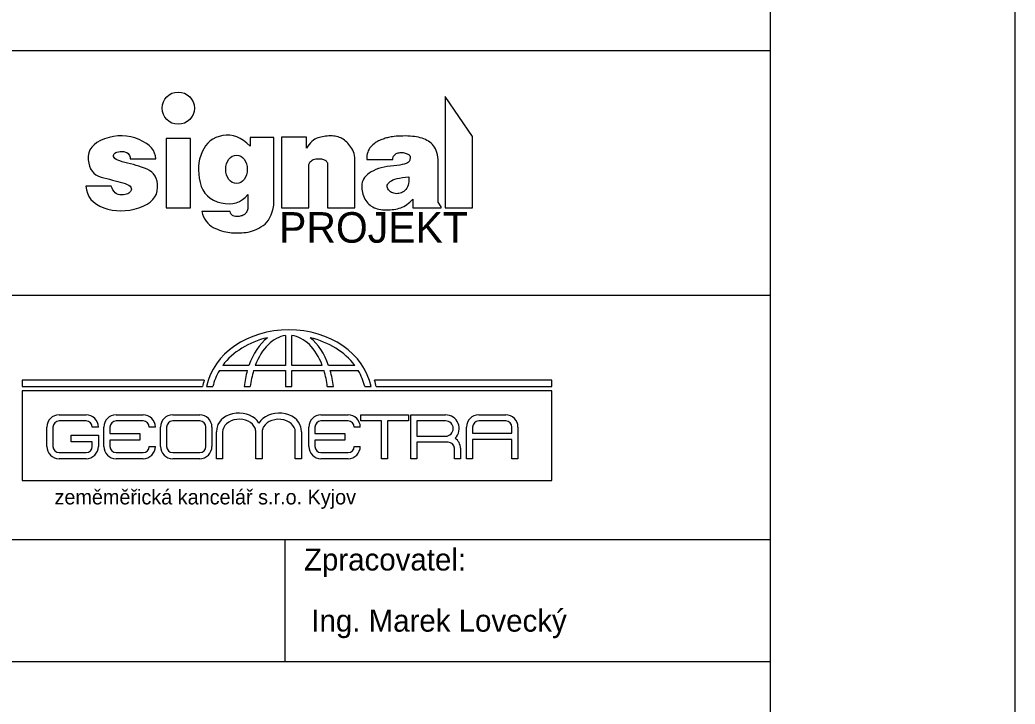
# Model space of a CAD drawing. Extents: x 2583 to 4283, y -3799 to -3355.
# Drawn here: x 3456.4 to 3537.7, y -3700 to -3644 of the extents above; entities that cross this region are included whole.
import ezdxf

# ---------------------------------------------------------------- set-up
doc = ezdxf.new("R2010")
doc.units = 0
for name, color, linetype in [('Default', 7, 'Continuous'), ('Vrstva 1', 7, 'Continuous'), ('Vrstva 11', 7, 'Continuous'), ('Vrstva 17', 7, 'Continuous'), ('Vrstva 6', 7, 'Continuous')]:
    doc.layers.add(name, color=color, linetype=linetype)

msp = doc.modelspace()

# ---------------------------------------------------------------- linework, layer by layer
at = {"layer": 'Default'}
msp.add_lwpolyline([(3327.684, -3798.543), (3537.684, -3798.543), (3537.684, -3501.543), (3327.684, -3501.543)], close=True, dxfattribs=at)
at = {"layer": 'Vrstva 1'}
msp.add_lwpolyline([(3347.684, -3521.543), (3517.684, -3521.543), (3517.684, -3781.543), (3347.684, -3781.543)], close=True, dxfattribs=at)
at = {"layer": 'Vrstva 11'}
for points in [[(3493.348, -3659.422), (3493.348, -3653.582), (3491.108, -3650.302), (3491.108, -3659.422), (3493.348, -3659.422)], [(3464.62, -3659.657), (3464.982, -3659.641), (3465.348, -3659.593), (3465.719, -3659.514), (3466.095, -3659.403), (3466.45, -3659.267), (3466.758, -3659.111), (3467.019, -3658.935), (3467.233, -3658.739), (3467.4, -3658.523), (3467.521, -3658.287), (3467.594, -3658.031), (3467.621, -3657.755), (3467.61, -3657.482), (3467.572, -3657.233), (3467.506, -3657.009), (3467.412, -3656.809), (3467.291, -3656.635), (3467.141, -3656.485), (3466.964, -3656.359), (3466.76, -3656.259), (3466.54, -3656.172), (3466.318, -3656.091), (3466.094, -3656.013), (3465.868, -3655.94), (3465.639, -3655.872), (3465.408, -3655.808), (3465.174, -3655.748), (3464.939, -3655.693), (3464.717, -3655.638), (3464.526, -3655.579), (3464.365, -3655.515), (3464.235, -3655.448), (3464.135, -3655.377), (3464.065, -3655.302), (3464.026, -3655.223), (3464.018, -3655.14), (3464.034, -3655.06), (3464.071, -3654.991), (3464.127, -3654.933), (3464.203, -3654.886), (3464.299, -3654.85), (3464.414, -3654.825), (3464.55, -3654.81), (3464.705, -3654.806), (3464.86, -3654.817), (3464.996, -3654.846), (3465.111, -3654.893), (3465.205, -3654.959), (3465.28, -3655.043), (3465.335, -3655.145), (3465.369, -3655.266), (3465.384, -3655.404), (3467.463, -3655.404), (3467.444, -3655.163), (3467.381, -3654.933), (3467.276, -3654.716), (3467.128, -3654.512), (3466.938, -3654.32), (3466.704, -3654.141), (3466.427, -3653.975), (3466.108, -3653.822), (3465.766, -3653.692), (3465.421, -3653.598), (3465.073, -3653.538), (3464.723, -3653.513), (3464.37, -3653.523), (3464.014, -3653.568), (3463.656, -3653.648), (3463.295, -3653.762), (3462.957, -3653.904), (3462.668, -3654.067), (3462.427, -3654.251), (3462.235, -3654.454), (3462.091, -3654.679), (3461.997, -3654.924), (3461.95, -3655.189), (3461.953, -3655.475), (3461.992, -3655.757), (3462.058, -3656.008), (3462.151, -3656.231), (3462.269, -3656.424), (3462.414, -3656.587), (3462.585, -3656.721), (3462.782, -3656.825), (3463.005, -3656.9), (3463.24, -3656.96), (3463.471, -3657.019), (3463.699, -3657.079), (3463.923, -3657.138), (3464.143, -3657.196), (3464.36, -3657.255), (3464.573, -3657.313), (3464.783, -3657.371), (3464.975, -3657.43), (3465.136, -3657.495), (3465.267, -3657.564), (3465.366, -3657.637), (3465.435, -3657.715), (3465.473, -3657.797), (3465.48, -3657.884), (3465.456, -3657.976), (3465.409, -3658.064), (3465.348, -3658.14), (3465.273, -3658.205), (3465.183, -3658.258), (3465.079, -3658.299), (3464.96, -3658.329), (3464.827, -3658.348), (3464.68, -3658.354), (3464.532, -3658.344), (3464.396, -3658.311), (3464.272, -3658.255), (3464.161, -3658.176), (3464.062, -3658.075), (3463.976, -3657.951), (3463.902, -3657.805), (3463.84, -3657.637), (3461.76, -3657.637), (3461.804, -3657.943), (3461.887, -3658.225), (3462.01, -3658.483), (3462.173, -3658.717), (3462.375, -3658.926), (3462.617, -3659.112), (3462.898, -3659.273), (3463.219, -3659.409), (3463.562, -3659.518), (3463.91, -3659.596), (3464.263, -3659.642), (3464.62, -3659.657)], [(3470.308, -3659.422), (3470.308, -3653.742), (3468.308, -3653.742), (3468.308, -3659.422), (3470.308, -3659.422)], [(3474.168, -3661.464), (3474.336, -3661.461), (3474.506, -3661.452), (3474.678, -3661.439), (3474.852, -3661.42), (3475.026, -3661.393), (3475.2, -3661.354), (3475.374, -3661.303), (3475.547, -3661.24), (3475.72, -3661.164), (3475.893, -3661.077), (3476.066, -3660.977), (3476.238, -3660.865), (3476.402, -3660.735), (3476.551, -3660.583), (3476.683, -3660.407), (3476.8, -3660.208), (3476.901, -3659.986), (3476.986, -3659.741), (3477.055, -3659.473), (3477.108, -3659.182), (3477.108, -3653.662), (3475.188, -3653.662), (3475.188, -3654.382), (3474.922, -3654.128), (3474.652, -3653.914), (3474.377, -3653.742), (3474.098, -3653.611), (3473.815, -3653.521), (3473.528, -3653.473), (3473.236, -3653.465), (3472.94, -3653.498), (3472.653, -3653.567), (3472.388, -3653.664), (3472.144, -3653.789), (3471.922, -3653.943), (3471.722, -3654.125), (3471.544, -3654.336), (3471.388, -3654.575), (3471.253, -3654.843), (3471.142, -3655.129), (3471.057, -3655.422), (3470.998, -3655.722), (3470.965, -3656.03), (3470.958, -3656.344), (3470.977, -3656.666), (3471.022, -3656.995), (3471.093, -3657.331), (3471.193, -3657.654), (3471.325, -3657.945), (3471.491, -3658.203), (3471.689, -3658.428), (3471.92, -3658.621), (3472.183, -3658.781), (3472.479, -3658.909), (3472.808, -3659.003), (3473.144, -3659.061), (3473.463, -3659.079), (3473.763, -3659.055), (3474.046, -3658.991), (3474.312, -3658.886), (3474.559, -3658.741), (3474.789, -3658.555), (3475, -3658.328), (3475, -3659.405), (3474.982, -3659.492), (3474.959, -3659.574), (3474.931, -3659.65), (3474.899, -3659.72), (3474.863, -3659.784), (3474.822, -3659.843), (3474.776, -3659.896), (3474.726, -3659.943), (3474.67, -3659.985), (3474.608, -3660.021), (3474.538, -3660.052), (3474.461, -3660.078), (3474.377, -3660.098), (3474.286, -3660.113), (3474.188, -3660.122), (3474.083, -3660.126), (3473.979, -3660.121), (3473.886, -3660.102), (3473.802, -3660.07), (3473.729, -3660.025), (3473.666, -3659.967), (3473.614, -3659.895), (3473.571, -3659.811), (3473.539, -3659.712), (3471.232, -3659.712), (3471.301, -3659.94), (3471.384, -3660.149), (3471.481, -3660.339), (3471.592, -3660.51), (3471.717, -3660.663), (3471.855, -3660.797), (3472.008, -3660.912), (3472.174, -3661.009), (3472.346, -3661.091), (3472.517, -3661.166), (3472.686, -3661.231), (3472.854, -3661.288), (3473.02, -3661.337), (3473.185, -3661.376), (3473.348, -3661.408), (3473.51, -3661.43), (3473.672, -3661.446), (3473.835, -3661.457), (3474.001, -3661.463), (3474.168, -3661.464)], [(3483.748, -3659.422), (3483.748, -3655.622), (3483.745, -3655.452), (3483.731, -3655.289), (3483.706, -3655.132), (3483.671, -3654.982), (3483.625, -3654.839), (3483.568, -3654.702), (3483.5, -3654.572), (3483.421, -3654.448), (3483.336, -3654.332), (3483.249, -3654.223), (3483.16, -3654.124), (3483.069, -3654.032), (3482.976, -3653.948), (3482.881, -3653.873), (3482.784, -3653.806), (3482.685, -3653.747), (3482.583, -3653.696), (3482.477, -3653.652), (3482.366, -3653.614), (3482.251, -3653.584), (3482.131, -3653.56), (3482.008, -3653.544), (3481.88, -3653.534), (3481.748, -3653.531), (3481.614, -3653.535), (3481.481, -3653.543), (3481.35, -3653.556), (3481.22, -3653.574), (3481.091, -3653.597), (3480.963, -3653.624), (3480.836, -3653.657), (3480.711, -3653.695), (3480.587, -3653.743), (3480.466, -3653.808), (3480.347, -3653.889), (3480.231, -3653.987), (3480.116, -3654.101), (3480.005, -3654.232), (3479.895, -3654.379), (3479.788, -3654.542), (3479.788, -3653.622), (3477.748, -3653.622), (3477.748, -3659.422), (3479.988, -3659.422), (3479.988, -3655.862), (3480.023, -3655.771), (3480.067, -3655.69), (3480.121, -3655.619), (3480.186, -3655.558), (3480.26, -3655.507), (3480.344, -3655.466), (3480.438, -3655.435), (3480.542, -3655.414), (3480.648, -3655.401), (3480.749, -3655.394), (3480.844, -3655.393), (3480.934, -3655.399), (3481.019, -3655.41), (3481.099, -3655.428), (3481.173, -3655.451), (3481.242, -3655.481), (3481.305, -3655.516), (3481.359, -3655.554), (3481.404, -3655.596), (3481.442, -3655.642), (3481.471, -3655.691), (3481.492, -3655.745), (3481.504, -3655.801), (3481.508, -3655.862), (3481.508, -3659.422), (3483.748, -3659.422)], [(3486.311, -3659.586), (3486.473, -3659.583), (3486.63, -3659.575), (3486.784, -3659.56), (3486.933, -3659.54), (3487.077, -3659.514), (3487.217, -3659.483), (3487.353, -3659.446), (3487.485, -3659.402), (3487.614, -3659.351), (3487.741, -3659.29), (3487.866, -3659.218), (3487.99, -3659.135), (3488.112, -3659.043), (3488.232, -3658.94), (3488.351, -3658.826), (3488.468, -3658.702), (3488.468, -3659.422), (3490.788, -3659.422), (3490.788, -3659.342), (3490.548, -3658.942), (3490.548, -3655.462), (3490.522, -3655.257), (3490.486, -3655.067), (3490.441, -3654.892), (3490.386, -3654.73), (3490.321, -3654.584), (3490.247, -3654.451), (3490.164, -3654.334), (3490.071, -3654.23), (3489.97, -3654.137), (3489.862, -3654.052), (3489.749, -3653.973), (3489.629, -3653.901), (3489.503, -3653.836), (3489.37, -3653.778), (3489.232, -3653.727), (3489.087, -3653.683), (3488.935, -3653.645), (3488.776, -3653.612), (3488.609, -3653.586), (3488.436, -3653.565), (3488.255, -3653.55), (3488.067, -3653.541), (3487.872, -3653.537), (3487.67, -3653.539), (3487.471, -3653.545), (3487.287, -3653.554), (3487.118, -3653.564), (3486.963, -3653.577), (3486.823, -3653.592), (3486.698, -3653.609), (3486.588, -3653.629), (3486.492, -3653.65), (3486.404, -3653.674), (3486.314, -3653.7), (3486.224, -3653.727), (3486.134, -3653.757), (3486.042, -3653.788), (3485.95, -3653.822), (3485.857, -3653.857), (3485.764, -3653.894), (3485.671, -3653.936), (3485.578, -3653.985), (3485.487, -3654.04), (3485.397, -3654.102), (3485.308, -3654.171), (3485.22, -3654.247), (3485.132, -3654.33), (3485.046, -3654.419), (3484.966, -3654.517), (3484.897, -3654.624), (3484.838, -3654.74), (3484.791, -3654.866), (3484.754, -3655.001), (3484.728, -3655.145), (3484.713, -3655.299), (3484.708, -3655.462), (3486.828, -3655.462), (3486.844, -3655.366), (3486.868, -3655.278), (3486.901, -3655.2), (3486.942, -3655.132), (3486.992, -3655.072), (3487.051, -3655.021), (3487.118, -3654.98), (3487.194, -3654.948), (3487.275, -3654.923), (3487.356, -3654.906), (3487.437, -3654.894), (3487.519, -3654.889), (3487.602, -3654.891), (3487.685, -3654.899), (3487.769, -3654.914), (3487.853, -3654.935), (3487.933, -3654.961), (3488.005, -3654.989), (3488.067, -3655.019), (3488.121, -3655.051), (3488.166, -3655.085), (3488.203, -3655.121), (3488.23, -3655.16), (3488.249, -3655.2), (3488.26, -3655.243), (3488.265, -3655.289), (3488.264, -3655.338), (3488.257, -3655.389), (3488.243, -3655.443), (3488.223, -3655.5), (3488.197, -3655.56), (3488.165, -3655.622), (3488.114, -3655.684), (3488.033, -3655.74), (3487.921, -3655.79), (3487.78, -3655.836), (3487.608, -3655.876), (3487.405, -3655.91), (3487.173, -3655.94), (3486.91, -3655.964), (3486.638, -3655.991), (3486.378, -3656.028), (3486.131, -3656.076), (3485.896, -3656.134), (3485.673, -3656.203), (3485.463, -3656.283), (3485.265, -3656.373), (3485.079, -3656.474), (3484.91, -3656.582), (3484.761, -3656.695), (3484.634, -3656.812), (3484.527, -3656.933), (3484.442, -3657.06), (3484.377, -3657.19), (3484.333, -3657.325), (3484.31, -3657.465), (3484.302, -3657.607), (3484.303, -3657.747), (3484.313, -3657.886), (3484.332, -3658.024), (3484.36, -3658.16), (3484.397, -3658.296), (3484.443, -3658.43), (3484.498, -3658.563), (3484.561, -3658.691), (3484.631, -3658.811), (3484.708, -3658.921), (3484.791, -3659.023), (3484.882, -3659.115), (3484.98, -3659.199), (3485.084, -3659.274), (3485.196, -3659.34), (3485.314, -3659.398), (3485.438, -3659.448), (3485.568, -3659.49), (3485.704, -3659.525), (3485.847, -3659.552), (3485.995, -3659.571), (3486.15, -3659.582), (3486.311, -3659.586)], [(3487.027, -3658.242), (3486.924, -3658.221), (3486.829, -3658.193), (3486.742, -3658.157), (3486.663, -3658.113), (3486.593, -3658.062), (3486.53, -3658.003), (3486.475, -3657.936), (3486.428, -3657.862), (3486.394, -3657.784), (3486.376, -3657.707), (3486.375, -3657.631), (3486.39, -3657.556), (3486.423, -3657.482), (3486.472, -3657.409), (3486.538, -3657.336), (3486.62, -3657.265), (3486.724, -3657.196), (3486.852, -3657.133), (3487.006, -3657.076), (3487.185, -3657.023), (3487.389, -3656.976), (3487.619, -3656.934), (3487.873, -3656.898), (3488.153, -3656.867), (3488.157, -3657.065), (3488.149, -3657.247), (3488.127, -3657.413), (3488.092, -3657.563), (3488.045, -3657.696), (3487.984, -3657.814), (3487.911, -3657.915), (3487.825, -3658), (3487.731, -3658.071), (3487.636, -3658.131), (3487.539, -3658.179), (3487.44, -3658.215), (3487.339, -3658.239), (3487.237, -3658.252), (3487.133, -3658.253), (3487.027, -3658.242)]]:
    msp.add_lwpolyline(points, dxfattribs=at)
msp.add_circle((3469.308, -3651.262), 1.32, dxfattribs=at)
msp.add_ellipse((3474.068, -3656.262), major_axis=(0, 1.16), ratio=0.758621, dxfattribs=at)
at = {"layer": 'Vrstva 17'}
for p, q in [((3478.079, -3669.856), (3478.079, -3672.301)), ((3478.586, -3672.301), (3478.586, -3669.853)), ((3472.665, -3672.713), (3474.953, -3672.713)), ((3475.085, -3672.301), (3472.94, -3672.301)), ((3475.463, -3672.713), (3478.079, -3672.713)), ((3478.079, -3672.301), (3475.602, -3672.301)), ((3478.079, -3672.713), (3478.079, -3674.033)), ((3481.08, -3672.301), (3478.586, -3672.301)), ((3478.586, -3674.033), (3478.586, -3672.713)), ((3478.586, -3672.713), (3481.22, -3672.713)), ((3483.742, -3672.301), (3481.597, -3672.301)), ((3481.73, -3672.713), (3484.017, -3672.713)), ((3471.434, -3673.502), (3456.554, -3673.502)), ((3456.554, -3673.502), (3456.554, -3674.033)), ((3499.832, -3673.502), (3485.354, -3673.502)), ((3499.832, -3674.033), (3499.832, -3673.502)), ((3499.831, -3674.378), (3456.548, -3674.378)), ((3456.548, -3674.378), (3456.548, -3681.716)), ((3456.554, -3674.033), (3471.297, -3674.033)), ((3471.622, -3674.033), (3472.139, -3674.033)), ((3474.696, -3674.033), (3475.196, -3674.033)), ((3478.079, -3674.033), (3478.586, -3674.033)), ((3481.487, -3674.033), (3481.987, -3674.033)), ((3484.543, -3674.033), (3485.06, -3674.033)), ((3485.492, -3674.033), (3499.832, -3674.033)), ((3499.831, -3681.716), (3499.831, -3674.378)), ((3459.573, -3676.344), (3461.783, -3676.344)), ((3461.783, -3676.842), (3459.573, -3676.842)), ((3464.229, -3676.344), (3466.44, -3676.344)), ((3466.44, -3676.842), (3464.229, -3676.842)), ((3468.853, -3676.344), (3471.063, -3676.344)), ((3471.063, -3676.842), (3468.853, -3676.842)), ((3480.971, -3676.344), (3483.182, -3676.344)), ((3483.182, -3676.842), (3480.971, -3676.842)), ((3485.914, -3679.925), (3485.914, -3676.83)), ((3486.418, -3676.83), (3486.418, -3679.925)), ((3488.309, -3676.344), (3491.153, -3676.344)), ((3491.153, -3676.832), (3488.813, -3676.832)), ((3488.813, -3676.832), (3488.813, -3678.082)), ((3493.857, -3676.344), (3496.068, -3676.344)), ((3496.068, -3676.842), (3493.857, -3676.842)), ((3458.575, -3678.928), (3458.575, -3677.341)), ((3459.074, -3677.341), (3459.074, -3678.928)), ((3462.781, -3677.341), (3462.282, -3677.341)), ((3463.231, -3678.928), (3463.231, -3677.341)), ((3463.73, -3677.341), (3463.73, -3677.852)), ((3467.437, -3677.341), (3466.939, -3677.341)), ((3467.855, -3678.928), (3467.855, -3677.341)), ((3468.354, -3677.341), (3468.354, -3678.928)), ((3471.563, -3678.928), (3471.563, -3677.341)), ((3472.061, -3677.341), (3472.061, -3678.928)), ((3472.434, -3679.925), (3472.434, -3677.741)), ((3472.934, -3677.741), (3472.934, -3679.925)), ((3475.654, -3679.925), (3475.654, -3677.741)), ((3476.154, -3677.741), (3476.154, -3679.925)), ((3478.873, -3679.925), (3478.873, -3677.741)), ((3479.373, -3677.741), (3479.373, -3679.925)), ((3479.974, -3678.928), (3479.974, -3677.341)), ((3480.472, -3677.341), (3480.472, -3677.852)), ((3484.18, -3677.341), (3483.681, -3677.341)), ((3492.859, -3679.925), (3492.859, -3677.341)), ((3493.358, -3677.341), (3493.358, -3677.85)), ((3496.567, -3677.85), (3496.567, -3677.341)), ((3497.065, -3677.341), (3497.065, -3679.925)), ((3460.548, -3678.549), (3460.548, -3678.005)), ((3460.548, -3678.005), (3462.781, -3678.005)), ((3462.282, -3678.549), (3460.548, -3678.549)), ((3462.282, -3678.928), (3462.282, -3678.549)), ((3462.781, -3678.005), (3462.781, -3678.928)), ((3463.73, -3677.852), (3466.173, -3677.852)), ((3466.173, -3678.397), (3463.73, -3678.397)), ((3463.73, -3678.397), (3463.73, -3678.928)), ((3466.173, -3677.852), (3466.173, -3678.397)), ((3480.472, -3677.852), (3482.915, -3677.852)), ((3482.915, -3678.397), (3480.472, -3678.397)), ((3480.472, -3678.397), (3480.472, -3678.928)), ((3482.915, -3677.852), (3482.915, -3678.397)), ((3488.813, -3678.082), (3491.153, -3678.082)), ((3491.153, -3678.571), (3488.813, -3678.571)), ((3491.367, -3678.575), (3491.153, -3678.571)), ((3493.358, -3677.85), (3496.567, -3677.85)), ((3496.567, -3678.354), (3493.358, -3678.354)), ((3493.358, -3678.354), (3493.358, -3679.925)), ((3496.567, -3679.925), (3496.567, -3678.354)), ((3466.939, -3678.928), (3467.437, -3678.928)), ((3483.681, -3678.928), (3484.18, -3678.928)), ((3491.866, -3679.925), (3491.866, -3679.074)), ((3492.365, -3679.074), (3492.365, -3679.925)), ((3459.573, -3679.427), (3461.783, -3679.427)), ((3461.783, -3679.925), (3459.573, -3679.925)), ((3464.229, -3679.427), (3466.44, -3679.427)), ((3466.44, -3679.925), (3464.229, -3679.925)), ((3468.853, -3679.427), (3471.063, -3679.427)), ((3471.063, -3679.925), (3468.853, -3679.925)), ((3472.934, -3679.925), (3472.434, -3679.925)), ((3476.154, -3679.925), (3475.654, -3679.925)), ((3479.373, -3679.925), (3478.873, -3679.925)), ((3480.971, -3679.427), (3483.182, -3679.427)), ((3483.182, -3679.925), (3480.971, -3679.925)), ((3486.418, -3679.925), (3485.914, -3679.925)), ((3492.365, -3679.925), (3491.866, -3679.925)), ((3493.358, -3679.925), (3492.859, -3679.925)), ((3497.065, -3679.925), (3496.567, -3679.925)), ((3456.548, -3681.716), (3499.831, -3681.716))]:
    msp.add_line(p, q, dxfattribs=at)
for points in [[(3485.914, -3676.83), (3484.216, -3676.83), (3484.216, -3676.344), (3488.13, -3676.344)], [(3488.13, -3676.344), (3488.13, -3676.83), (3486.418, -3676.83)], [(3488.813, -3678.571), (3488.813, -3679.925), (3488.309, -3679.925), (3488.309, -3676.344)]]:
    msp.add_lwpolyline(points, dxfattribs=at)
for centre, radius, start, end in [((3459.573, -3677.341), 0.998, 90, 180), ((3459.573, -3677.341), 0.499, 90, 180), ((3461.783, -3677.341), 0.998, 360, 90), ((3461.783, -3677.341), 0.499, 0, 90), ((3464.229, -3677.341), 0.998, 90, 180), ((3464.229, -3677.341), 0.499, 90, 180), ((3466.44, -3677.341), 0.998, 360, 90), ((3466.44, -3677.341), 0.499, 0, 90), ((3468.853, -3677.341), 0.998, 90, 180), ((3468.853, -3677.341), 0.499, 90, 180), ((3471.063, -3677.341), 0.998, 360, 90), ((3471.063, -3677.341), 0.499, 0, 90), ((3480.971, -3677.341), 0.998, 90, 180), ((3480.971, -3677.341), 0.499, 90, 180), ((3483.182, -3677.341), 0.998, 360, 90), ((3483.182, -3677.341), 0.499, 0, 90), ((3491.153, -3677.457), 1.114, 314.45734, 90), ((3491.153, -3677.457), 0.625, 270, 90), ((3493.857, -3677.341), 0.998, 90, 180), ((3493.857, -3677.341), 0.499, 90, 180), ((3496.068, -3677.341), 0.998, 360, 90), ((3496.068, -3677.341), 0.499, 0, 90), ((3474.371, -3677.791), 1.938, 166.96576, 178.52091), ((3474.699, -3677.805), 0.957, 3.86486, 22.41569), ((3477.387, -3677.862), 1.238, 162.61388, 174.3506), ((3477.436, -3677.791), 1.938, 1.47909, 13.03424), ((3491.367, -3679.074), 0.499, 0, 90), ((3491.367, -3679.074), 0.998, 360, 55.44734), ((3459.573, -3678.928), 0.998, 180, 270), ((3459.573, -3678.928), 0.499, 180, 270), ((3461.783, -3678.928), 0.998, 270, 0), ((3461.783, -3678.928), 0.499, 270, 0), ((3464.229, -3678.928), 0.998, 180, 270), ((3464.229, -3678.928), 0.499, 180, 270), ((3466.44, -3678.928), 0.998, 270, 0), ((3466.44, -3678.928), 0.499, 270, 0), ((3468.853, -3678.928), 0.998, 180, 270), ((3468.853, -3678.928), 0.499, 180, 270), ((3471.063, -3678.928), 0.998, 270, 0), ((3471.063, -3678.928), 0.499, 270, 0), ((3480.971, -3678.928), 0.998, 180, 270), ((3480.971, -3678.928), 0.499, 180, 270), ((3483.182, -3678.928), 0.998, 270, 0), ((3483.182, -3678.928), 0.499, 270, 0)]:
    msp.add_arc(centre, radius, start, end, dxfattribs=at)
for centre, major_axis, ratio, start_param, end_param in [((3478.341, -3674.906), (-6.804, 0), 0.811768, 3.300239, 6.124539), ((3478.341, -3674.906), (-6.296, 0), 0.804826, 4.992897, 5.743383), ((3478.341, -3674.906), (0, 5.524), 0.668443, 0.491666, 1.079789), ((3478.341, -3674.906), (0, 5.067), 0.630136, 0.08224, 1.030995), ((3478.341, -3674.906), (0, 5.067), 0.630136, 5.252191, 6.206521), ((3478.341, -3674.906), (0, 5.524), 0.668443, 5.203397, 5.79152), ((3478.341, -3674.906), (-6.296, 0), 0.804826, 3.681394, 4.431881), ((3478.341, -3674.906), (-6.296, 0), 0.804826, 5.835664, 6.110118), ((3478.341, -3674.906), (0, 5.524), 0.668443, 1.16256, 1.41215), ((3478.341, -3674.906), (0, 5.067), 0.630136, 1.123275, 1.397729), ((3478.341, -3674.906), (0, 5.067), 0.630136, 4.885456, 5.159911), ((3478.341, -3674.906), (0, 5.524), 0.668443, 4.871035, 5.120625), ((3478.341, -3674.906), (-6.296, 0), 0.804826, 3.31466, 3.589114), ((3478.015, -3674.906), (-6.804, 0), 0.811768, 6.026233, 6.124539), ((3478.773, -3674.906), (-6.804, 0), 0.811768, 3.300239, 3.398545), ((3474.263, -3677.585), (1.805, 0), 0.766187, 0.429647, 2.97338), ((3477.544, -3677.585), (-1.805, 0), 0.766187, 3.309805, 5.853538), ((3474.288, -3677.741), (1.354, 0), 0.766187, 0.29376, 3.141593), ((3477.519, -3677.741), (-1.354, 0), 0.766187, 3.141593, 6.041607)]:
    msp.add_ellipse(centre, major_axis=major_axis, ratio=ratio, start_param=start_param, end_param=end_param, dxfattribs=at)
at = {"layer": 'Vrstva 6'}
for p, q in [((3347.684, -3666.543), (3517.684, -3666.543)), ((3347.684, -3686.543), (3517.684, -3686.543)), ((3478.034, -3696.543), (3478.034, -3686.543))]:
    msp.add_line(p, q, dxfattribs=at)
msp.add_lwpolyline([(3347.684, -3646.543), (3517.684, -3646.543), (3517.684, -3696.543), (3347.684, -3696.543)], close=True, dxfattribs=at)

# ---------------------------------------------------------------- texts
at = {"layer": 'Vrstva 11'}
msp.add_text('PROJEKT', height=2.5, dxfattribs=at).set_placement((3477.549, -3662.265))
at = {"layer": 'Vrstva 17'}
msp.add_text('zeměměřická kancelář s.r.o. Kyjov', height=1.20984, dxfattribs=at).set_placement((3459.199, -3683.665))
at = {"layer": 'Vrstva 6'}
for s, p in [('Zpracovatel:', (3479.58, -3689.069)), ('Ing. Marek Lovecký', (3480.181, -3694.069))]:
    msp.add_text(s, height=1.8, dxfattribs=at).set_placement(p)

doc.saveas('drawing.dxf')
